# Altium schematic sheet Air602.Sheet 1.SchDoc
size 431 x 279 mm
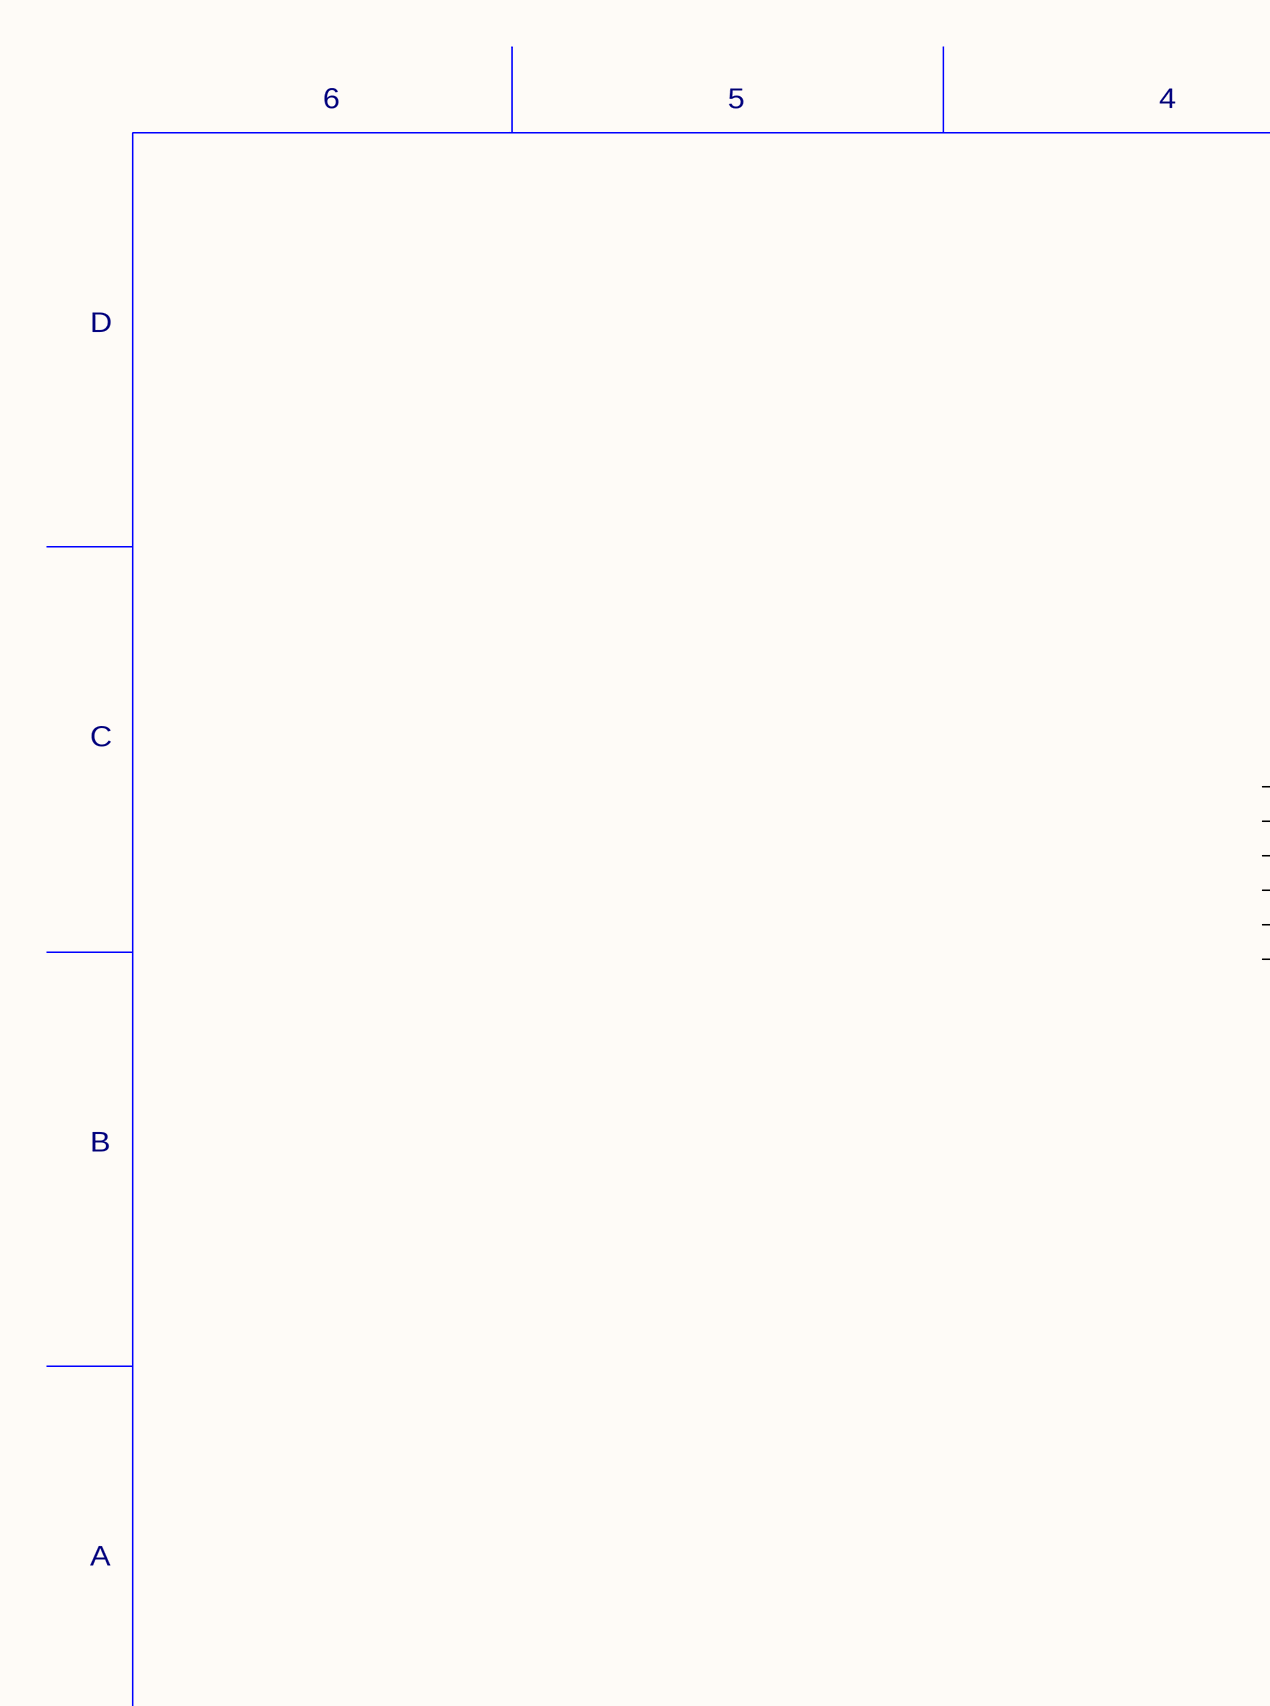
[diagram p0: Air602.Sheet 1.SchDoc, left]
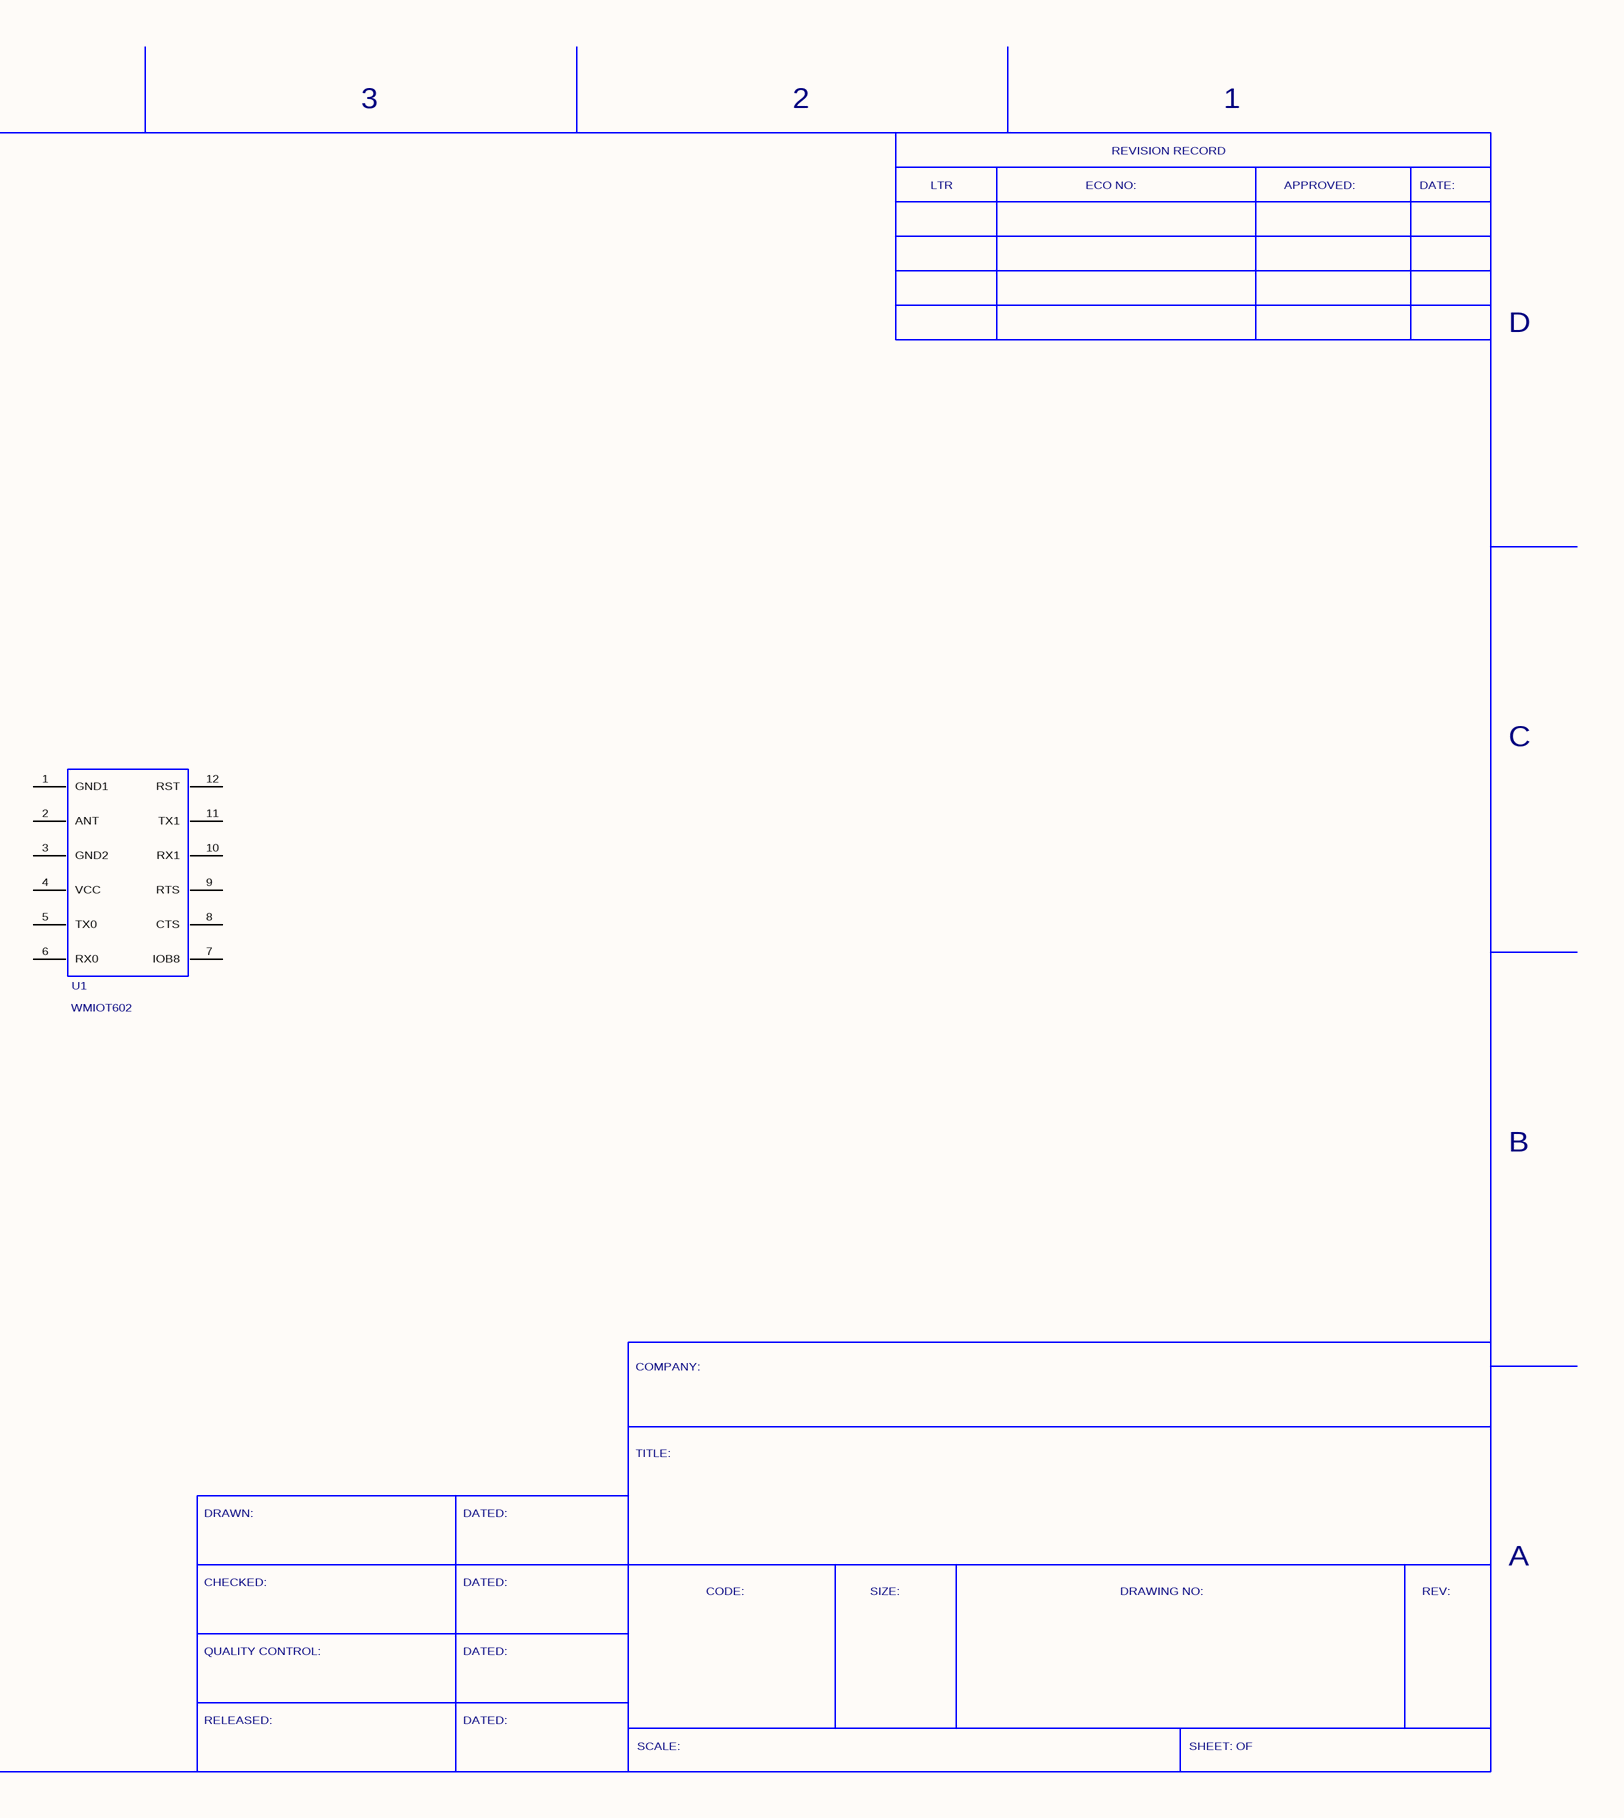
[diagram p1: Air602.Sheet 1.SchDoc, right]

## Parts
U1  WMIOT602  [WMIOT602]

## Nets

Not connected (* = marked no-connect by the designer): U1 1(GND1) 2(ANT) 3(GND2) 4(VCC) 5(TX0) 6(RX0) 7(IOB8) 8(CTS) 9(RTS) 10(RX1) 11(TX1) 12(RST)

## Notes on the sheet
- 6
- 5
- 4
- 3
- 2
- REVISION RECORD
- 1
- LTR
- ECO NO:
- APPROVED:
- DATE:
- D
- C
- B
- COMPANY:
- TITLE:
- DRAWN:
- DATED:
- A
- CHECKED:
- CODE:
- SIZE:
- DRAWING NO:
- REV:
- QUALITY CONTROL:
- RELEASED:
- SCALE:
- SHEET: OF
